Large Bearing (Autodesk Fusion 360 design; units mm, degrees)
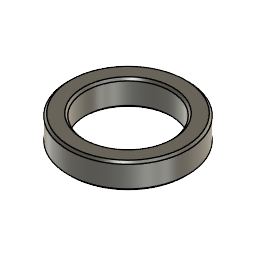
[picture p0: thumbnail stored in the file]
part number: 2025-12-16-10-52-09-464
sketch "Sketch1" plane through (0, 0, 0) normal (0, 0, 1) x axis (1, 0, 0)
  circle C1 centre (0, 0) radius 5
  circle C2 centre (0, 0) radius 7
  point P1 (0, 0)
  point P2 (0, 0)
  coincident P1 P2
  concentric C1 C2
  dimension "d1" diameter C2 = 14
  dimension "d2" diameter C1 = 10
extrude "Extrude1" new body sketch "Sketch1" along normal blind 3
chamfer "Chamfer1" distance 0.25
